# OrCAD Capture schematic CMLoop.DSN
size C
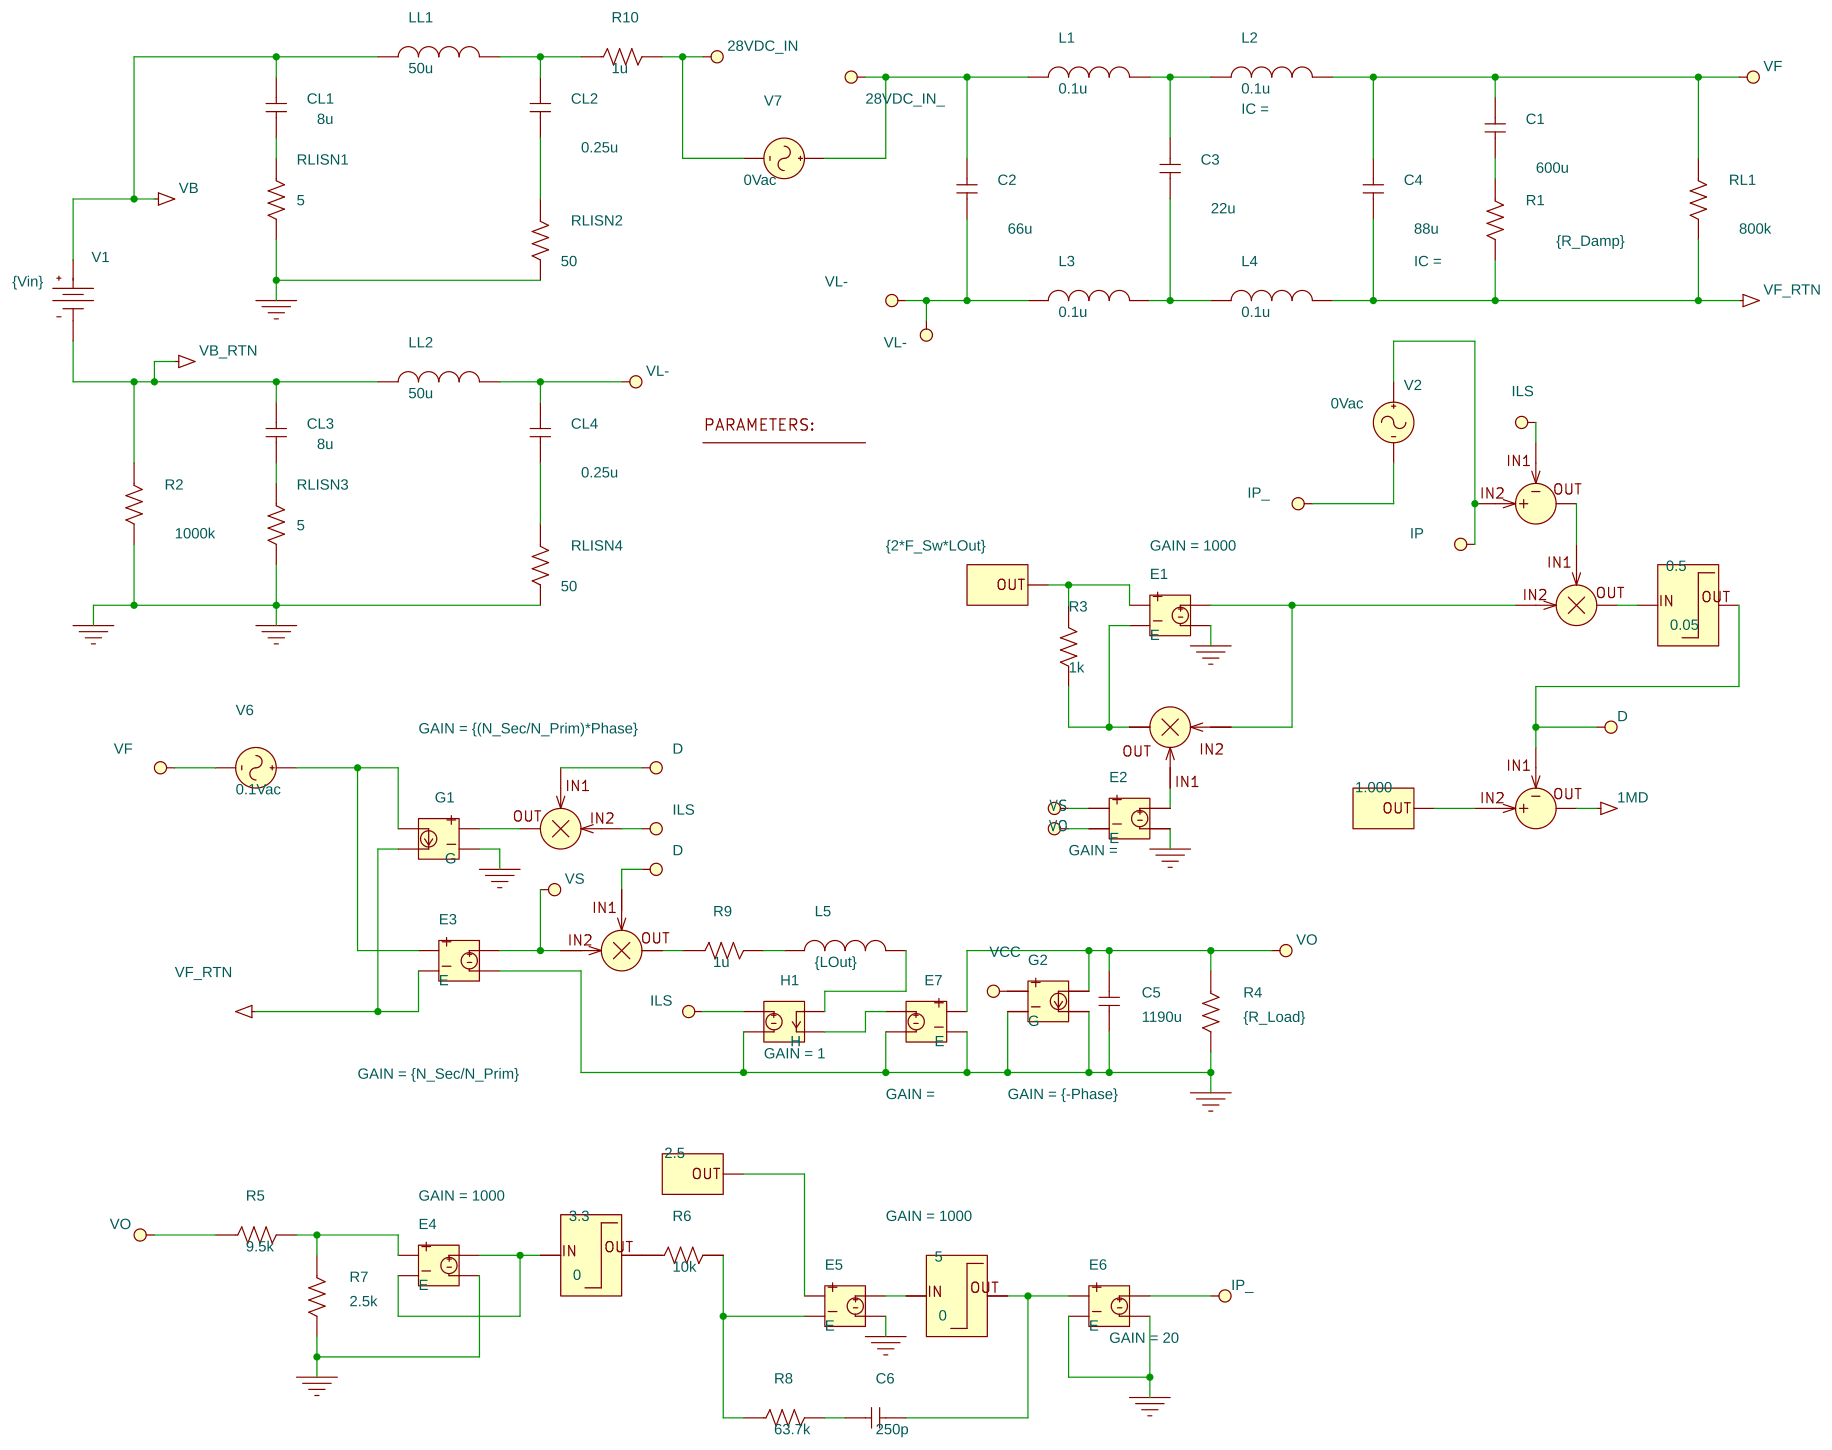
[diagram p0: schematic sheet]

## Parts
?#1  PARAM
C1  600u  [CK05]
C2  66u  [CK05]
C3  22u  [CK05]
C4  88u  [CK05]
C5  1190u  [CK05]
C6  250p  [RAD/CK05]
CL1  8u  [CK05]
CL2  0.25u  [CK05]
CL3  8u  [CK05]
CL4  0.25u  [CK05]
CONST1  {2*F_Sw*LOut}
CONST2  1.000
CONST3  2.5
DIFF1  DIFF
DIFF2  DIFF
E1  E
E2  E
E3  E
E4  E
E5  E
E6  E
E7  E
G1  G
G2  G
H1  H
L1  0.1u  [L2012C]
L2  0.1u  [L2012C]
L3  0.1u  [L2012C]
L4  0.1u  [L2012C]
L5  {LOut}  [L2012C]
LIMIT1  LIMIT
LIMIT2  LIMIT
LIMIT3  LIMIT
LL1  50u  [L2012C]
LL2  50u  [L2012C]
MULT1  MULT
MULT2  MULT
MULT3  MULT
MULT4  MULT
R1  {R_Damp}  [RC05]
R2  1000k  [RC05]
R3  1k  [AX/RC05]
R4  {R_Load}  [RC05]
R5  9.5k  [AX/RC05]
R6  10k  [AX/RC05]
R7  2.5k  [AX/RC05]
R8  63.7k  [AX/RC05]
R9  1u  [AX/RC05]
R10  1u  [AX/RC05]
RL1  800k  [RC05]
RLISN1  5  [RC05]
RLISN2  50  [RC05]
RLISN3  5  [RC05]
RLISN4  50  [RC05]
V1  VDC
V2  VAC
V6  VAC
V7  VAC

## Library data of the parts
?#1 = PARAM: F_Sw: 300k; LOut: 4.4u; N_Prim: 4; N_Sec: 8; Phase: 2; R_Damp: 0.3; R_Load: 0.192; Vin: 28
C1-C6 CL1-CL4 = C
CONST1-CONST3 = CONST
DIFF1 DIFF2 = DIFF
E1 E4 E5 = E: GAIN: 1000
E2 E7 = E
E3 = E: GAIN: {N_Sec/N_Prim}
E6 = E: GAIN: 20
G1 = G: GAIN: {(N_Sec/N_Prim)*Phase}
G2 = G: GAIN: {-Phase}
H1 = H: GAIN: 1
L1-L5 LL1 LL2 = L_v2
LIMIT1 = LIMIT: HI: 0.5; LO: 0.05
LIMIT2 = LIMIT: HI: 3.3; LO: 0
LIMIT3 = LIMIT: HI: 5; LO: 0
MULT1-MULT4 = MULT
R1-R10 RL1 RLISN1-RLISN4 = R
V1 = VDC: DC: {Vin}
V2 V7 = VAC: ACMAG: 0Vac
V6 = VAC: ACMAG: 0.1Vac

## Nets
28VDC_IN: R10.2 V7.2(-)
28VDC_IN_: C2.1 L1.1 V7.1(+)
0: C5.2 E1.4 E2.4 E3.4 E4.4 E5.4 E6.2 E6.4 E7.2 E7.4 G1.2 G2.2 G2.4 H1.4 R2.2 R4.2 R7.2 RLISN1.2 RLISN2.2 RLISN3.2 RLISN4.2
1mD: DIFF2.5(OUT)
D: DIFF2.1(IN1) LIMIT1.2(OUT) MULT3.1(IN1) MULT4.1(IN1)
DC_IN_RTN: C2.2 CL4.1 L3.1 LL2.2
ILS: DIFF1.1(IN1) G2.1 H1.3 MULT3.3(IN2)
Ip: DIFF1.3(IN2) V2.1(+)
Ip_: E6.3 V2.2(-)
Vb: CL1.1 LL1.1 V1.0(+)
Vb_rtn: CL3.1 LL2.1 R2.1 V1.1(-)
VF: C1.1 C4.1 L2.2 RL1.1 V6.2(-)
VF_RTN: C4.2 E3.2 G1.4 L4.2 R1.2 RL1.2
Vo: C5.1 E2.2 E7.1 G2.3 R4.1 R5.1
Vs: E2.1 E3.3 MULT4.3(IN2)
N63099: C3.1 L1.2 L2.1
N63239: C1.2 R1.1
N63253: C3.2 L3.2 L4.1
N63787: DIFF1.5(OUT) MULT1.1(IN1)
N63885: CL2.1 LL1.2 R10.1
N63901: CONST1.5(OUT) E1.1 R3.1
N63947: E1.3 MULT1.3(IN2) MULT2.3(IN2)
N63961: LIMIT1.1(IN) MULT1.5(OUT)
N64025: E1.2 MULT2.5(OUT) R3.2
N64049: CL1.2 RLISN1.1
N64055: CL2.2 RLISN2.1
N64129: E3.1 G1.3 V6.1(+)
N64297: G1.1 MULT3.5(OUT)
N64387: E2.3 MULT2.1(IN1)
N64487: CONST2.5(OUT) DIFF2.3(IN2)
N64645: H1.1 L5.2
N64903: CL3.2 RLISN3.1
N64909: CL4.2 RLISN4.1
N65061: CONST3.5(OUT) E5.1
N65139: E4.1 R5.2 R7.1
N65207: E4.2 E4.3 LIMIT2.1(IN)
N65221: E5.2 R6.2 R8.1
N65337: E5.3 LIMIT3.1(IN)
N65343: C6.2 E6.1 LIMIT3.2(OUT)
N65481: C6.1 R8.2
N74858: E7.3 H1.2
N74947: MULT4.5(OUT) R9.1
N74951: L5.1 R9.2
N78238: LIMIT2.2(OUT) R6.1
